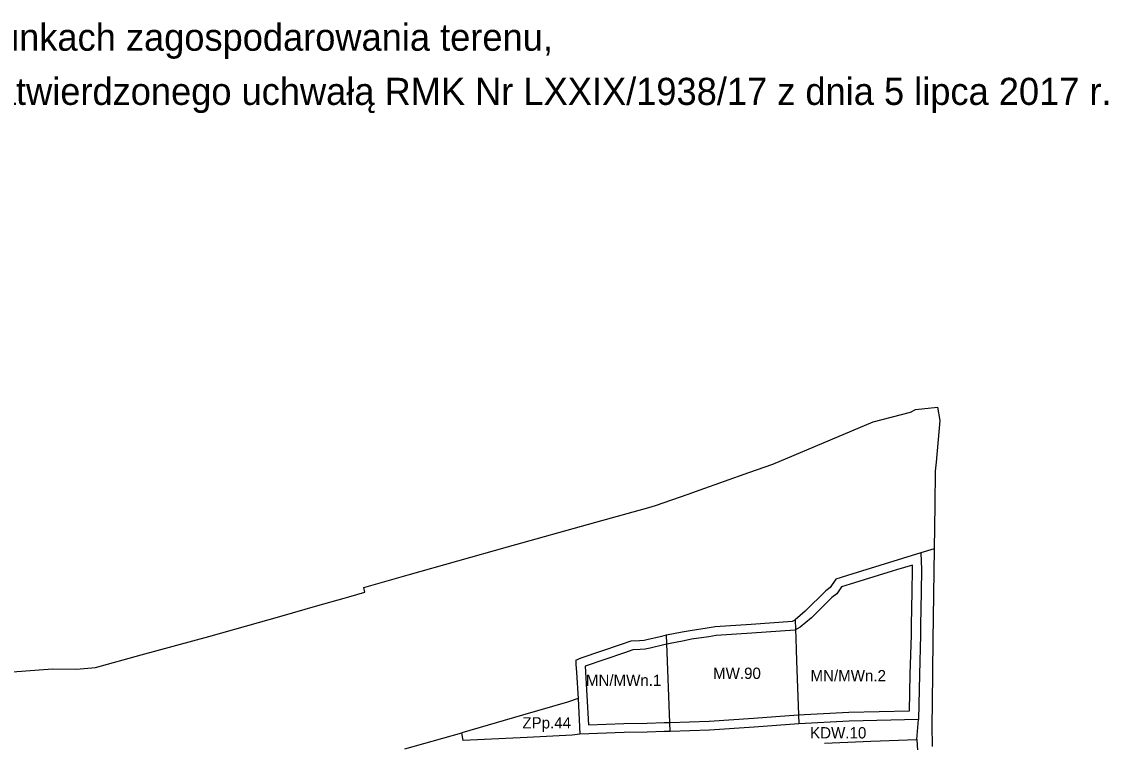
# Model space of a CAD drawing. Extents: x 7424434 to 7425898, y 5541432 to 5542659.
# Drawn here: x 7425417.1 to 7425898.3, y 5542339.7 to 5542658.8 of the extents above; entities that cross this region are included whole.
import ezdxf

# ---------------------------------------------------------------- set-up
doc = ezdxf.new("R2010")
doc.units = 0
for name, color, linetype in [('info', 7, 'Continuous'), ('linie rozgraniczające', 7, 'Continuous'), ('nieprzekraczalne linie zabudowy', 7, 'Continuous'), ('przeznaczenia terenów', 7, 'Continuous')]:
    doc.layers.add(name, color=color, linetype=linetype)

msp = doc.modelspace()

# ---------------------------------------------------------------- linework, layer by layer
at = {"layer": 'linie rozgraniczające'}
for p, q in [((7425812.9, 5542487.01), (7425822.71, 5542488.13)), ((7425822.71, 5542488.13), (7425823.72, 5542482.24)), ((7425794.15, 5542481.62), (7425810.69, 5542485.9)), ((7425810.69, 5542485.9), (7425812.9, 5542487.01)), ((7425749.78, 5542462.88), (7425794.15, 5542481.62)), ((7425823.72, 5542482.24), (7425822.09, 5542463.74)), ((7425717.64, 5542451.53), (7425739.21, 5542459.15)), ((7425739.21, 5542459.15), (7425749.78, 5542462.88)), ((7425821.74, 5542459.78), (7425821.53, 5542444.76)), ((7425822.09, 5542463.74), (7425821.74, 5542459.78)), ((7425697.8, 5542444.52), (7425712.25, 5542449.63)), ((7425712.25, 5542449.63), (7425717.64, 5542451.53)), ((7425694.81, 5542443.7), (7425697.8, 5542444.52)), ((7425821.53, 5542444.73), (7425821.25, 5542425.37)), ((7425821.53, 5542444.76), (7425821.53, 5542444.73)), ((7425671.41, 5542437.17), (7425694.81, 5542443.7)), ((7425632.28, 5542426.27), (7425671.41, 5542437.17)), ((7425588.21, 5542413.83), (7425632.28, 5542426.27)), ((7425821.25, 5542425.37), (7425815.35, 5542423.55)), ((7425821.25, 5542425.37), (7425820.67, 5542384.89)), ((7425815.35, 5542423.55), (7425789.06, 5542415.43)), ((7425815.35, 5542423.55), (7425815.68, 5542416.21)), ((7425815.68, 5542416.21), (7425815.49, 5542406.35)), ((7425568.6, 5542408.27), (7425588.21, 5542413.83)), ((7425777.61, 5542411.89), (7425775.13, 5542408.23)), ((7425782.79, 5542413.49), (7425777.61, 5542411.89)), ((7425789.06, 5542415.43), (7425782.79, 5542413.49)), ((7425562, 5542404.15), (7425569.01, 5542406.25)), ((7425569.01, 5542406.25), (7425568.6, 5542408.27)), ((7425773.26, 5542406.76), (7425764.14, 5542397.72)), ((7425775.13, 5542408.23), (7425773.26, 5542406.76)), ((7425815.49, 5542406.35), (7425815.21, 5542391.44)), ((7425548.21, 5542400.27), (7425559.94, 5542403.57)), ((7425559.94, 5542403.57), (7425562, 5542404.15)), ((7425531.49, 5542395.36), (7425548.21, 5542400.27)), ((7425764.14, 5542397.72), (7425759.71, 5542393.98)), ((7425499.96, 5542386.57), (7425521.97, 5542392.71)), ((7425521.97, 5542392.71), (7425531.49, 5542395.36)), ((7425724.26, 5542390.97), (7425740.23, 5542392.08)), ((7425740.23, 5542392.08), (7425758.46, 5542393.35)), ((7425758.46, 5542393.35), (7425759.71, 5542393.98)), ((7425759.71, 5542393.98), (7425759.99, 5542385.66)), ((7425700.61, 5542386.76), (7425702.7, 5542387.24)), ((7425702.7, 5542387.24), (7425709.68, 5542388.56)), ((7425704.25, 5542344.48), (7425702.7, 5542387.24)), ((7425709.68, 5542388.56), (7425713.12, 5542389.24)), ((7425713.12, 5542389.24), (7425720.75, 5542390.42)), ((7425720.75, 5542390.42), (7425724.26, 5542390.97)), ((7425815.13, 5542387.07), (7425814.67, 5542369.73)), ((7425815.21, 5542391.44), (7425815.13, 5542387.07)), ((7425470.02, 5542378.45), (7425499.96, 5542386.57)), ((7425664.86, 5542377.06), (7425682.73, 5542383.14)), ((7425682.73, 5542383.14), (7425686.96, 5542384.58)), ((7425686.96, 5542384.58), (7425690.77, 5542384.81)), ((7425690.77, 5542384.81), (7425692.73, 5542384.93)), ((7425692.73, 5542384.93), (7425694.59, 5542385.33)), ((7425694.59, 5542385.33), (7425700.61, 5542386.76)), ((7425759.99, 5542385.66), (7425760.15, 5542380.68)), ((7425820.67, 5542384.89), (7425820.3, 5542356.83)), ((7425449.78, 5542372.88), (7425470.02, 5542378.45)), ((7425760.15, 5542380.68), (7425760.31, 5542375.75)), ((7425441.29, 5542372.09), (7425449.78, 5542372.88)), ((7425662.46, 5542376.03), (7425664.86, 5542377.06)), ((7425662.46, 5542376.03), (7425662.56, 5542374.36)), ((7425662.56, 5542374.36), (7425662.79, 5542370.53)), ((7425760.31, 5542375.75), (7425761.23, 5542347.93)), ((7425413.01, 5542370.87), (7425430.78, 5542372.25)), ((7425430.78, 5542372.25), (7425441.29, 5542372.09)), ((7425662.79, 5542370.53), (7425663.48, 5542359.04)), ((7425814.67, 5542369.73), (7425814.25, 5542349.76)), ((7425663.48, 5542359.04), (7425658.77, 5542357.48)), ((7425663.48, 5542359.04), (7425664.31, 5542343.33)), ((7425658.77, 5542357.48), (7425638.9, 5542351.76)), ((7425820.3, 5542356.83), (7425820.13, 5542347.32)), ((7425638.9, 5542351.76), (7425612.05, 5542343.91)), ((7425783.61, 5542349.01), (7425761.23, 5542347.93)), ((7425814.25, 5542349.76), (7425783.61, 5542349.01)), ((7425813.48, 5542341), (7425814.25, 5542349.76)), ((7425586.82, 5542336.84), (7425612.05, 5542343.91)), ((7425612.69, 5542340.52), (7425612.05, 5542343.91)), ((7425683.86, 5542344.04), (7425664.31, 5542343.33)), ((7425694.18, 5542344.19), (7425683.86, 5542344.04)), ((7425701.68, 5542344.42), (7425694.18, 5542344.19)), ((7425704.25, 5542344.48), (7425701.68, 5542344.42)), ((7425721.7, 5542345.11), (7425704.25, 5542344.48)), ((7425741.44, 5542346.35), (7425721.7, 5542345.11)), ((7425761.23, 5542347.93), (7425741.44, 5542346.35)), ((7425820.13, 5542347.32), (7425820.33, 5542337.89)), ((7425640.95, 5542341.89), (7425612.69, 5542340.52)), ((7425660.95, 5542342.9), (7425640.95, 5542341.89)), ((7425664.31, 5542343.33), (7425660.95, 5542342.9)), ((7425772.68, 5542339.36), (7425789.77, 5542340.05)), ((7425789.77, 5542340.05), (7425793.22, 5542340.19)), ((7425793.22, 5542340.19), (7425813.48, 5542341)), ((7425813.48, 5542341), (7425815.61, 5542310.78))]:
    msp.add_line(p, q, dxfattribs=at)
at = {"layer": 'nieprzekraczalne linie zabudowy'}
for points in [[(7425811.21, 5542391.52), (7425811.49, 5542406.43), (7425811.68, 5542416.16), (7425811.59, 5542418.2), (7425804.59, 5542416.04), (7425802.66, 5542415.44), (7425790.24, 5542411.61), (7425783.97, 5542409.67), (7425780.13, 5542408.48), (7425778.09, 5542405.47), (7425775.91, 5542403.76), (7425766.84, 5542394.77), (7425761.93, 5542390.62), (7425759.54, 5542389.42), (7425740.51, 5542388.09), (7425724.71, 5542386.99), (7425721.37, 5542386.47), (7425713.81, 5542385.3), (7425710.44, 5542384.63), (7425703.52, 5542383.32), (7425701.52, 5542382.86), (7425695.47, 5542381.43), (7425693.28, 5542380.96), (7425691.01, 5542380.82), (7425687.74, 5542380.62), (7425684.02, 5542379.35), (7425666.64, 5542373.47)], [(7425666.63, 5542373.47), (7425666.64, 5542373.47), (7425668.1, 5542347.47), (7425683.76, 5542348.04), (7425694.09, 5542348.19), (7425701.57, 5542348.42), (7425704.14, 5542348.48), (7425721.5, 5542349.11), (7425741.16, 5542350.34), (7425760.97, 5542351.92), (7425783.46, 5542353.01), (7425810.33, 5542353.67), (7425810.67, 5542369.83), (7425811.13, 5542387.16), (7425811.21, 5542391.51), (7425811.21, 5542391.51)]]:
    msp.add_lwpolyline(points, dxfattribs=at)
msp.add_arc((7425815.21, 5542391.44), 4, 178.925, 178.9521, dxfattribs=at)

# ---------------------------------------------------------------- texts
at = {"layer": 'info'}
for s, p in [('Materiał pomocniczy zawierający linie rozgraniczające teren o różnym przeznaczeniu i różnych warunkach zagospodarowania terenu, ', (7424704.25, 5542645.97)), ('opracowane w skali 1:1000 pochodzące z Miejscowego Planu Zagospodarowania Przestrzennego obszaru "OSIEDLE KURDWANÓW" zatwierdzonego uchwałą RMK Nr LXXIX/1938/17 z dnia 5 lipca 2017 r.', (7424433.64, 5542621.97))]:
    msp.add_text(s, height=12, dxfattribs=at).set_placement(p)
at = {"layer": 'przeznaczenia terenów'}
for s, p in [('MW.90', (7425723.3, 5542367.76)), ('MN/MWn.1', (7425666.97, 5542364.67)), ('MN/MWn.2', (7425766.45, 5542366.69)), ('ZPp.44', (7425638.84, 5542345.82)), ('KDW.10', (7425766.28, 5542341.4))]:
    msp.add_text(s, height=5, dxfattribs=at).set_placement(p)

doc.saveas('drawing.dxf')
